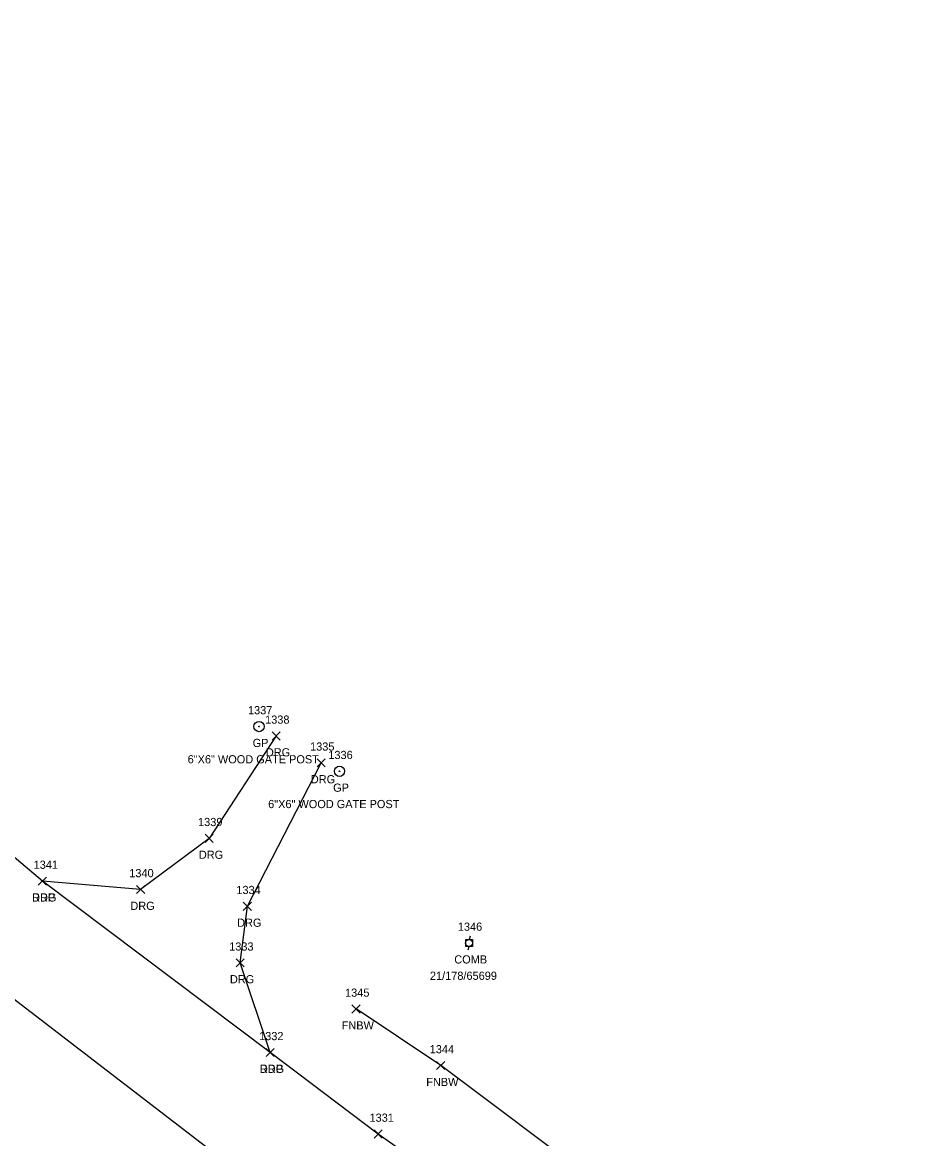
# Model space of a CAD drawing. Extents: x 1503463 to 1505240, y 712171 to 717196.
# Drawn here: x 1503961.3 to 1504181, y 715346.9 to 715619.9 of the extents above; entities that cross this region are included whole.
import ezdxf

# ---------------------------------------------------------------- set-up
doc = ezdxf.new("R2010")
doc.units = 0
for name, color, linetype in [('L_A', 7, 'Continuous'), ('L_I', 7, 'Continuous'), ('L_TIC', 7, 'Continuous'), ('LFNC', 7, 'Continuous'), ('P_A', 7, 'Continuous'), ('P_I', 7, 'Continuous'), ('P_TIC', 7, 'Continuous'), ('PET', 7, 'Continuous'), ('R_A', 7, 'Continuous'), ('R_C', 7, 'Continuous'), ('R_I', 7, 'Continuous'), ('R_TIC', 7, 'Continuous'), ('RDG', 7, 'Continuous'), ('RGP', 7, 'Continuous'), ('U_A', 7, 'Continuous'), ('U_C', 7, 'Continuous'), ('U_I', 7, 'Continuous'), ('UP', 7, 'Continuous')]:
    doc.layers.add(name, color=color, linetype=linetype)

msp = doc.modelspace()

# ---------------------------------------------------------------- linework, layer by layer
at = {"layer": 'L_TIC'}
for points in [[(1504041.83, 715377.65), (1504043.83, 715379.65)], [(1504043.83, 715377.65), (1504041.83, 715379.65)], [(1504062.51, 715363.82), (1504064.51, 715365.82)], [(1504064.51, 715363.82), (1504062.51, 715365.82)]]:
    msp.add_lwpolyline(points, dxfattribs=at)
at = {"layer": 'LFNC'}
msp.add_lwpolyline([(1504181.03, 715274.63), (1504142.65, 715304.71), (1504101.77, 715336.16), (1504063.51, 715364.82), (1504042.83, 715378.65)], dxfattribs=at)
at = {"layer": 'P_TIC'}
for points in [[(1503965.17, 715408.92), (1503967.17, 715410.92)], [(1503967.17, 715408.92), (1503965.17, 715410.92)], [(1504020.82, 715367.03), (1504022.82, 715369.03)], [(1504022.82, 715367.03), (1504020.82, 715369.03)], [(1504047.23, 715347.08), (1504049.23, 715349.08)], [(1504049.23, 715347.08), (1504047.23, 715349.08)]]:
    msp.add_lwpolyline(points, dxfattribs=at)
at = {"layer": 'PET'}
for points in [[(1504086.6, 715320.97), (1504048.23, 715348.08), (1504021.82, 715368.03), (1503966.17, 715409.92), (1503923.82, 715445.68), (1503891.58, 715474.62), (1503849.62, 715517.03), (1503813.69, 715557.19), (1503785.7, 715592.4), (1503758.96, 715629.69), (1503731.53, 715672.92), (1503706.38, 715717.5), (1503684.24, 715763.13), (1503664.14, 715810.3), (1503646.76, 715858.44), (1503630.24, 715911.59)], [(1504010.26, 715341.79), (1503951.37, 715387.03), (1503906.51, 715423.33), (1503870.54, 715455.93), (1503828.42, 715498.53), (1503793.3, 715537.68), (1503762.47, 715576.59), (1503736.04, 715613.53), (1503707.39, 715658.39), (1503681.7, 715703.45), (1503658.24, 715752.13), (1503638.35, 715798.92), (1503620.07, 715849.48), (1503602.71, 715905.3)]]:
    msp.add_lwpolyline(points, dxfattribs=at)
at = {"layer": 'R_TIC'}
for points in [[(1504022.29, 715444.4), (1504024.29, 715446.4)], [(1504024.29, 715444.4), (1504022.29, 715446.4)], [(1504033.28, 715437.82), (1504035.28, 715439.82)], [(1504035.28, 715437.82), (1504033.28, 715439.82)], [(1504005.92, 715419.37), (1504007.92, 715421.37)], [(1504007.92, 715419.37), (1504005.92, 715421.37)], [(1503965.17, 715408.92), (1503967.17, 715410.92)], [(1503967.17, 715408.92), (1503965.17, 715410.92)], [(1503989.19, 715406.87), (1503991.19, 715408.87)], [(1503991.19, 715406.87), (1503989.19, 715408.87)], [(1504015.27, 715402.75), (1504017.27, 715404.75)], [(1504017.27, 715402.75), (1504015.27, 715404.75)], [(1504013.51, 715388.93), (1504015.51, 715390.93)], [(1504015.51, 715388.93), (1504013.51, 715390.93)], [(1504020.82, 715367.03), (1504022.82, 715369.03)], [(1504022.82, 715367.03), (1504020.82, 715369.03)]]:
    msp.add_lwpolyline(points, dxfattribs=at)
at = {"layer": 'RDG'}
for points in [[(1504023.29, 715445.4), (1504006.92, 715420.37), (1503990.19, 715407.87), (1503966.17, 715409.92)], [(1504021.82, 715368.03), (1504014.51, 715389.93), (1504016.27, 715403.75), (1504034.28, 715438.82)]]:
    msp.add_lwpolyline(points, dxfattribs=at)
at = {"layer": 'RGP'}
for p, q in [((1504019.11, 715447.7), (1504019.11, 715447.7)), ((1504038.79, 715436.76), (1504038.79, 715436.76))]:
    msp.add_line(p, q, dxfattribs=at)
for centre, radius in [((1504019.11, 715447.7), 1.25), ((1504019.11, 715447.7), 0.0833), ((1504038.79, 715436.76), 1.25), ((1504038.79, 715436.76), 0.0833)]:
    msp.add_circle(centre, radius, dxfattribs=at)
at = {"layer": 'UP'}
for p, q in [((1504070.69, 715396.44), (1504070.44, 715395.61)), ((1504069.61, 715393.94), (1504069.61, 715395.61)), ((1504069.61, 715395.61), (1504071.28, 715395.61)), ((1504071.28, 715393.94), (1504069.61, 715393.94)), ((1504070.19, 715393.11), (1504070.44, 715393.94)), ((1504070.44, 715394.78), (1504070.44, 715394.78)), ((1504071.28, 715395.61), (1504071.28, 715393.94))]:
    msp.add_line(p, q, dxfattribs=at)
msp.add_circle((1504070.44, 715394.78), 0.833, dxfattribs=at)

# ---------------------------------------------------------------- texts
at = {"layer": 'L_A'}
for p in [(1504039.31, 715373.65), (1504059.98, 715359.82)]:
    msp.add_text('FNBW', height=2, dxfattribs=at).set_placement(p)
at = {"layer": 'L_I'}
for s, p in [('1345', (1504040.14, 715381.65)), ('1344', (1504060.82, 715367.82))]:
    msp.add_text(s, height=2, dxfattribs=at).set_placement(p)
at = {"layer": 'P_A'}
for p in [(1503963.66, 715404.92), (1504019.31, 715363.03)]:
    msp.add_text('RDP', height=2, dxfattribs=at).set_placement(p)
at = {"layer": 'P_I'}
for s, p in [('1341', (1503964.04, 715412.92)), ('1332', (1504019.13, 715371.03)), ('1331', (1504046.11, 715351.08))]:
    msp.add_text(s, height=2, dxfattribs=at).set_placement(p)
at = {"layer": 'R_A'}
for s, p in [('GP', (1504017.55, 715442.7)), ('DRG', (1504020.78, 715440.4)), ('DRG', (1504031.77, 715433.82)), ('GP', (1504037.23, 715431.76)), ('DRG', (1504004.41, 715415.37)), ('DRG', (1503963.66, 715404.92)), ('DRG', (1503987.67, 715402.87)), ('DRG', (1504013.76, 715398.75)), ('DRG', (1504012, 715384.93)), ('DRG', (1504019.31, 715363.03))]:
    msp.add_text(s, height=2, dxfattribs=at).set_placement(p)
at = {"layer": 'R_C'}
for p in [(1504001.67, 715438.7), (1504021.35, 715427.76)]:
    msp.add_text('6"X6" WOOD GATE POST', height=2, dxfattribs=at).set_placement(p)
at = {"layer": 'R_I'}
for s, p in [('1337', (1504016.42, 715450.7)), ('1338', (1504020.6, 715448.4)), ('1335', (1504031.59, 715441.82)), ('1336', (1504036.05, 715439.76)), ('1339', (1504004.22, 715423.37)), ('1341', (1503964.04, 715412.92)), ('1340', (1503987.41, 715410.87)), ('1334', (1504013.58, 715406.75)), ('1333', (1504011.82, 715392.93)), ('1332', (1504019.13, 715371.03))]:
    msp.add_text(s, height=2, dxfattribs=at).set_placement(p)
at = {"layer": 'U_A'}
msp.add_text('COMB', height=2, dxfattribs=at).set_placement((1504066.83, 715389.78))
at = {"layer": 'U_C'}
msp.add_text('21/178/65699', height=2, dxfattribs=at).set_placement((1504060.88, 715385.78))
at = {"layer": 'U_I'}
msp.add_text('1346', height=2, dxfattribs=at).set_placement((1504067.7, 715397.78))

doc.saveas('drawing.dxf')
